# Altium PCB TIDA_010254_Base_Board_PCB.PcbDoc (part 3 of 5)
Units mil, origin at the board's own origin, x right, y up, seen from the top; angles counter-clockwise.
Board outline 3514.38 x 3143.81 mil, 4 copper layers (Top Layer, L2_GND1, L3_PWR1, Bottom Layer), stack 62.715 mil thick; 219 components, 146 nets, 618 pads, 2382 vias.
Unrouted connection lines stored in the file: 2280.
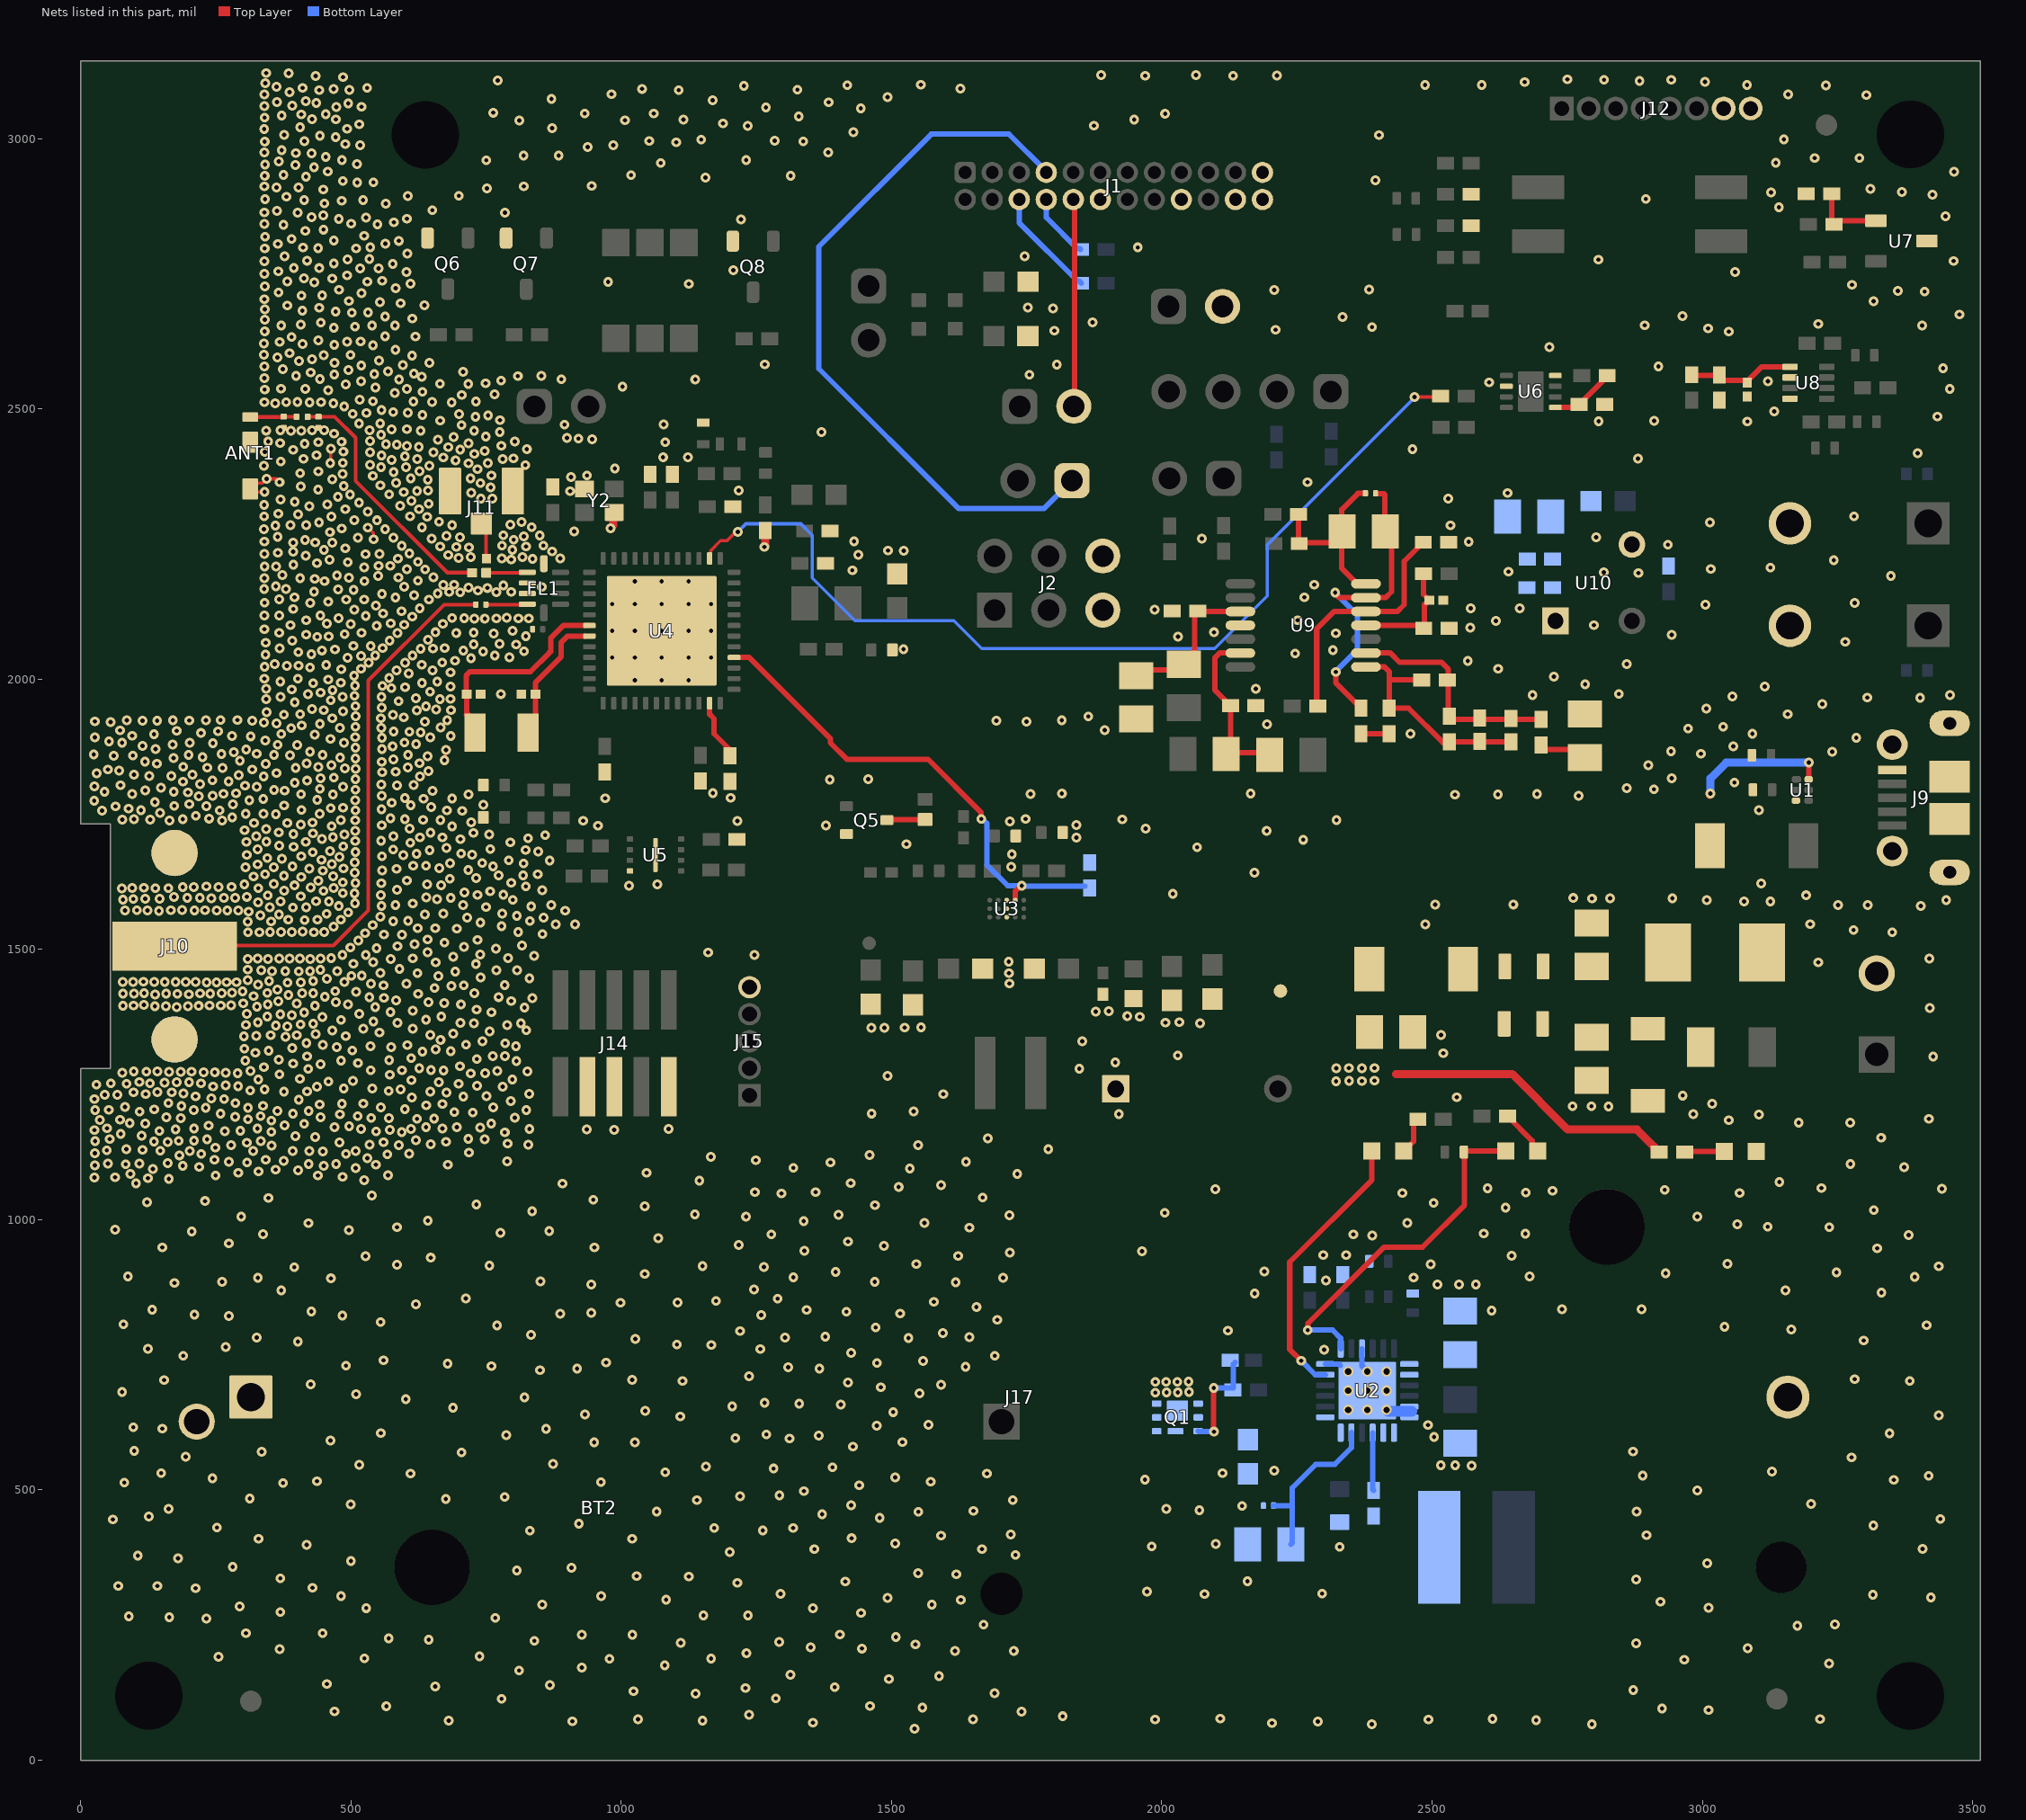
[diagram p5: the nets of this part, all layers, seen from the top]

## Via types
v1: diameter 18, hole 8, Top Layer to Bottom Layer, tented both sides, 2351 vias
v2: diameter 19.68, hole 7.87, Top Layer to Bottom Layer, 21 vias
v3: diameter 19.68, hole 11.81, Top Layer to Bottom Layer, 9 vias
v4: diameter 18, hole 8, Top Layer to Bottom Layer, tented bottom, 1 vias

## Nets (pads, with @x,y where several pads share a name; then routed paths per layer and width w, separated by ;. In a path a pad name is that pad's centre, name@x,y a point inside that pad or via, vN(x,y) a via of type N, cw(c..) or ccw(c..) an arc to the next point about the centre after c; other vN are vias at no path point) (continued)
GND: ANT1.2 ANT1.3 BT2.2 C1.2 C2.2 C4.2 C5.2 C6.2 C7.2 C8.2 C9.2 C10.2 C11.2 C12.2 C13.2 C14.2 C15.2 C16.2 C17.2 C18.2 C19.2 C20.2 C21.2 C22.2 C23.2 C24.2 C25.2 C27.1 C28.2 C32.2 C33.2 C34.2 C35.2 C36.2 C37.2 C38.2 C39.2 C40.2 C41.2 C42.2 C43.2 C44.2 C45.2 C47.2 C48.2 C49.1 C50.2 C51.2 C53.2 C55.2 C56.2 C57.2 C58.2 D6.2 D9.2 FL1.2 FL1.3 FL1.10 J1.12 J1.18 J1.22 J1.23 J1.24 J2.5 J2.6 J3.2 J8.2 J9.5 J9.6 J9.7 J9.8 J9.9 J9.10 J9.11 J10.2 J10.3 J10.4 J10.5 J11.2 J11.3 J12.7 J12.8 J14.3 J14.5 J14.9 J15.5 J17.1 Q5.2 Q6.2 Q7.2 Q8.2 R1.1 R2.1 R5.1 R10.1 R13.1 R16.1 R21.2 R22.1 R26.2 R31.2 R33.2 R36.1 R53.1 R59.1 R62.1 R75.1 R78.1 S1.2 S2.2 SW1.1 TP2.1 U1.3 U2.6 U2.9 U2.17 U2.18 U2.25 U3.C1 U3.C2 U3.C3 U4.49 U5.4 U5.9 U6.2 U6.8 U7.3 U8.2 U8.4 U9.11 U10.3 Y2.2 Y2.4 | length 368.6
  Top Layer w6: v1(289.66,1924.33) v1@290.3,1923.69 ; v1@316.49,1923.69 v1(317.13,1923.06) ; v1(324.89,1339.84) v1@325.59,1340.54 ; v1(339.32,2322.56) v1@340.36,2323.6 ; v1@340.74,2346.65 v1(340.36,2346.28) 319.25,2346.28 ANT1.2@313.66,2351.87 324.28,2362.49 336.02,2362.49 v1(344.15,2370.63) 361.66,2370.63 v1(367.83,2364.46) ; v1(341.99,2045.29) v1@342.05,2045.36 ; v1@342.05,2067.28 v1(342.12,2067.35) ; v1@350.89,1340.54 v1(351.58,1341.23) ; v1@364.18,2085.68 v1(367.12,2085.68) ; v1(417.3,2284.9) v1@417.84,2284.9 ; v1@455.89,2322.96 v1(456.43,2322.96) ; v1(461.77,2399.95) 462.43,2400.62 462.43,2425.93 v1(463.09,2426.6) ; v1(531.37,2280.34) 541.57,2270.14 541.57,2259.01 v1(541.94,2258.64) ; v1(574.96,2462) v1@575.16,2461.8 ; v1@575.16,2405.6 v1(575.36,2405.4) ; v1(609.39,2301.16) v1@609.39,2303.36 ; v1(673.09,1849.67) 674.58,1851.16 674.58,1867.47 v1(676.08,1868.96) ; v1(2794.73,1209.9) v1@2795.06,1209.58 ; v1@2826.17,1209.58 v1(2826.5,1209.26) ; v1@3404.02,1580.51 v1(3404.23,1580.51)
  Top Layer w10: ANT1.3@313.66,2438.48 314.2,2439.03 314.2,2439.26 ANT1.3@314.81,2439.87 ; v1@343.27,2443.35 v1(346.75,2439.87)
  Top Layer w15: v1(980.36,2279.08) 980.36,2279.9 985.48,2285.02 Y2.2@985.48,2307.51 ; v1(1264.52,2244.67) 1264.52,2245.48 1266.25,2247.21 C32.2@1266.25,2272.55
  Bottom Layer w6: 2460.02,648.33 2461.45,646.9
  Bottom Layer w10: U2.6@2302.44,732.97 2327.95,732.97 U2.25@2330.17,730.75 ; U2.9@2370.35,761.52 2370.35,729.04 v3(2380.19,719.19)
  Bottom Layer w20: U2.25@2418.41,645.89 2462.8,645.89
  other v1: 1542.39,58.46 2388.65,66.59 2795.65,66.73 2203.67,68.59 1354.37,69.52 909.53,71.98 2288.66,71.63 680.96,73.21 1150.38,73.21 2692.51,74.1 1987.42,75.24 2493.22,75.24 1031.18,75.67 1650.52,75.67 3217.6,76.18 2108.28,77.13 2611.81,76.38 1816.54,81.3 1236.4,84.27 1740.51,89.68 469.6,90.41 3011.7,92.88 2925.44,95.66 1557.09,97.26 565.48,100.06 1460.05,100.24 778.55,113.48 1286.04,114.32 1137.7,122.98 1690.65,124.21 1022.65,127.74 2872.08,129.57 1229.84,133.62 1394.88,135.12 656.07,136.28 867.91,139.13 455.6,141.17 1495.28,150.24 1587.85,155.54 1312.88,157.94 811.1,166.05 927.02,171.36 1080.53,175.56 3234.3,179.13 2966.44,185.95 978.1,187.58 1166.09,188.14 524.97,188.53 255.11,191.5 737.76,192.33 1231.74,198.03 1617.64,201.96 1726.12,201.96 368.23,205.63 1445.42,206.6 3084.04,206.96 1350.43,209.05 1544.4,214.14 2877.79,216.26 1110.15,217.03 1292.13,218.92 839.41,220.83 643.72,222.73 569.78,225.22 1507.95,227.82 927.24,232.27 1020.69,232.27 1404.67,232.66 305.72,235 447.53,235 3175.86,248.69 1670.3,250.86 3245.43,251.48 232.37,261.9 767.04,263.42 163.99,264.52 89.03,266.15 1151.96,267.87 1234.28,267.87 1443.43,272.32 369.29,274.12 1354.43,281.22 528.21,281.46 3011.7,282.08 294.14,284.47 853.81,287.89 1574.7,287.89 2922.66,293.21 1082.99,296.79 1628.05,296.5 1492.75,300.35 3422.64,301.17 481.76,303.46 962.84,303.47 3315.41,306 1294.71,307.92 2079.01,307.36 2296.5,308.11 1972.57,312.15 212.8,318.13 428.81,319.03 69.73,322.35 141.87,322.35 1214.74,328.23 1414.38,330.74 2158.43,331.29 2877.74,334.51 369.2,336.61 1124.98,339.97 1028.29,340.63 1619.67,343.85 1549.43,345.84 807,350.99 907.73,355.91 281.12,357.59 3009.04,364.16 500.05,368.49 180.36,373.38 105.8,378.56 1729.16,379.83 1200.76,385.07 1357.34,390.42 1667.33,390.49 3407.19,391.02 2329.12,394.83 1981.2,395.58 417.85,398.69 2099.61,399.93 1506.96,400.75 328.94,409.58 1020.13,409.59 1426.1,410.69 1591.87,415.44 2896.47,416.49 1720.37,417.64 830.88,424.66 1261.79,425.21 1171.96,429.72 1317.92,429.72 251.93,430.6 3316.37,434.49 921.52,437.55 59.5,445.38 3440.2,446.25 1478.24,448.29 126.08,450.63 1371.72,455.26 1065.59,460.02 1549.53,459.47 2878.27,460 1651.77,461.35 2069.42,462.71 162.84,464.96 2008.47,464.98 2148.49,470.5 1425.29,471.67 499.39,473.5 3200.91,474.08 1139.95,481.14 1724.26,481.14 312.83,483.97 675.37,483.41 784.42,486.95 1219.77,488.44 1292.63,490.06 1337.71,497.97 2990.89,499.17 1440.08,508.57 374.44,512.83 80.64,513.61 962.25,514.45 437.14,516.12 1572.59,515.39 1968.73,519.28 3353.94,518.6 243.73,521.58 1506.95,523.22 3418.78,526.27 2889.6,526.56 1676.63,530.19 149.04,531.01 609.94,530.38 2112.28,531.22 1081.36,532.9 3128.8,534.01 2208.15,535.68 1281.85,539.61 1390.72,541.82 1156.59,542.99 2573.17,545.12 2516.15,545.82 2542.79,545.59 515.15,546.32 873.58,548.07 3276.03,560.33 194.12,561.34 704.46,569.38 334.8,570.65 2871.54,571.19 99.09,572.33 1428.44,580.14 949.87,588.16 1025.39,588.02 1519.9,588.56 462.22,591.56 1211.18,596.03 1311.17,595.29 2503.74,597.89 1365.6,600.34 787.07,601.61 1268.53,602.59 555.18,605.08 3346.32,604.52 860.83,613.2 151.13,613.48 97.41,615.95 1472.77,618.86 2492.56,620.27 1568.15,620.54 1109.05,636.08 3437.42,638.24 932.89,639.43 1503.07,644.11 1044.48,646.59 688.79,652.02 1205.16,654.6 1406,658.13 1329.13,659.82 1265.06,661.46 601.55,667.95 821.06,671.46 509.28,677.18 1551.88,678.89 76.44,681.37 1480.06,690.12 1591.72,694.6 425.28,695.45 1419.46,698.53 1113.24,701.51 3383.57,701.67 154.46,703.18 1020.46,703.62 3281.6,705.02 1236.47,710.59 849.7,721.72 918.26,724.3 1366.72,724.34 1308.93,727.15 1636.93,727.61 760.09,729.19 490.76,730.07 678.67,733.73 1472.99,734.8 972.13,735.63 1558.26,738.67 560.34,739.8 189.76,748.15 1690.91,748.25 1425.08,753.52 2300.31,759.51 124.26,761.06 1257.37,760.71 268.31,764.44 1166.67,768.26 1102.91,769.02 401.91,774.48 3298.65,776.44 1026,779.52 1531.36,780.98 325.5,782.05 1302.76,782.13 1643.9,782.7 1377.38,783.82 833.23,786.73 1594.96,790.07 1219.78,794.06 2122.49,794.73 3164.73,796.84 1470.52,800.65 3040.87,801.93 770.17,804.52 3414.78,804.74 78.96,806.36 554.76,810.76 1695.52,814.68 273.93,821.8 484.24,822.91 210.36,824.25 1258.77,823.62 886.99,825.83 1515.98,826.41 944.31,827.45 426.77,830.24 1416.66,829.83 2610.04,831.67 1343.16,833.19 132.34,833.75 2887.54,834.14 2740.48,834.5 1657.08,838.6 620.2,843.38 998.78,846.27 1104.08,846.74 1578.16,848.13 1175.26,849.71 712.28,854.17 1289.29,853.95 2171.84,863.33 3331.31,864.99 371.12,869.19 3153.48,869.34 1245.59,870.86 2509.77,880 2549.66,880.19 2580.93,879.81 944.31,880.32 173.68,882.93 1618.65,884.25 261.79,884.9 1468.82,884.98 850.69,886.05 2303.64,887.48 462.94,891.45 327.72,892.71 1318.47,893.23 1706.18,892.67 2465.76,893.11 3392.9,894.23 87.35,895.28 2680.58,894.88 1043.25,899.56 2932.08,900.89 3248.21,902.58 1396.46,903.33 2189.91,904.32 395.15,911.95 1263.66,912.38 1150.49,914.08 3437.42,913.71 756.15,915.01 585.37,916.49 1546.03,917.97 2497.41,917.45 3046.66,918.2 647.78,929.72 526.94,932.66 1623.26,932.82 2647.19,933.19 2298.53,934.49 2341.06,934.69 1718.68,939.13 1963.68,941.8 1338.67,942.61 3323.34,947.1 151.13,948.58 950.58,948.63 1485.93,951.52 1217.52,953.18 273.93,956.28 1419.46,959.44 1068.35,965.59 2389.1,970.73 3381.39,971.69 1277.51,972.91 2354.2,972.86 337.5,973.39 2672.43,974.26 2595.56,974.38 776.25,975.52 205.47,978.28 866.74,978.87 496.33,980.49 63.86,981.68 1643.9,985.25 585.37,986.06 3234.77,986.2 3120.92,986.82 3064.56,991.62 421.5,993.47 1560.76,994 2454.27,993.87 1337.55,997.59 642.13,998.33 297.12,1005.64 1230.91,1005.53 2990.89,1005.8 1717.96,1008.25 1402.07,1008.81 1136.24,1010.03 2005.54,1012.79 835.09,1015.88 3317.17,1017.8 2636.06,1022.23 1043.5,1024.91 1469.11,1026.84 732.06,1028.29 2502.71,1030.91 122.95,1032.09 229.92,1034.52 948.29,1036.96 347.27,1040.32 1668.59,1040.94 538.42,1044.62 1296.59,1048.65 2444.92,1049.27 3068.92,1049.27 2673.25,1050.09 1247.21,1050.9 1359.43,1050.9 2722.71,1053.61 2930.43,1055.04 2099.15,1056.28 2602.78,1057.98 3443.18,1057.44 3220.38,1058.4 1513.18,1060.55 1591.72,1063.8 102.45,1067.24 891.44,1066.75 1424.51,1067.73 3142.47,1069.53 524.37,1072.84 1144.65,1072.31 162.92,1075.37 124.31,1076.64 25.56,1077.9 63.54,1078.54 484.49,1079.17 249.64,1081.7 438.91,1081.7 568.68,1082.33 92.03,1084.87 1732.55,1084.56 291.81,1086.85 1046.9,1086.79 328.77,1089.3 402.2,1091.2 360.42,1092.46 133.48,1094.08 1533.93,1094.66 508.54,1095.63 1318.47,1095.78 3373.41,1097.25 219.26,1097.53 188.87,1099.43 449.67,1099.43 26.19,1100.69 546.12,1101.76 679.06,1101.76 83.16,1102.59 421.82,1103.22 472.46,1103.22 3273.97,1103.06 50.25,1103.86 108.48,1103.86 161.02,1104.49 307.88,1105.76 1386.92,1105.88 274.33,1107.02 1637.73,1107.01 789.06,1108.09 375.61,1108.92 1248.99,1110.18 247.74,1110.82 342.06,1110.82 530.06,1113.98 1165.75,1116.32 182.54,1119.05 1459.43,1119.45 567.41,1120.95 223.06,1121.58 490.82,1121.58 26.12,1122.91 607.62,1122.34 718.16,1124.1 448.03,1126.14 201.53,1127.28 319.2,1127.09 392.27,1127.09 423.09,1127.28 508.83,1127.09 147.3,1127.45 48.28,1128.4 114.18,1129.18 84.51,1130.42 1790.02,1130.61 249.26,1133.35 352.91,1136.9 278.51,1137.97 588.32,1138.13 1549.08,1137.87 534.49,1138.67 827.84,1138.97 647.78,1139.74 789.66,1140.86 307.25,1142.47 478.79,1143.1 560.12,1143.23 161.02,1143.74 676.02,1144.18 135.7,1144.37 26.6,1145.49 181.4,1145.88 333.2,1145.63 209.74,1146.41 620.24,1146.84 53.74,1149.09 233.82,1148.8 747.26,1148.93 717.08,1149.38 1678.24,1150.51 3330.62,1151.6 433.71,1152.92 112.51,1155.27 397.04,1154.7 73.93,1158.9 593.9,1161.87 784.55,1161.71 352.6,1162.58 145.64,1164.22 266.76,1163.95 546.52,1163.36 295.19,1164.67 25.15,1165.9 986.81,1165.95 175.58,1167.16 571.64,1166.42 936.01,1166.92 518.5,1168 611.15,1168 830.25,1167.87 1087.44,1167.88 48.87,1169.13 209.74,1168.61 326.92,1168.93 669.28,1168.45 469.67,1171.13 638.85,1171.02 695.82,1171.02 738.85,1170.41 496.51,1172.85 236.73,1174.06 377.47,1174.63 119.53,1178.04 413.33,1177.39 759.5,1177.72 90.65,1178.65 3273.24,1179.27 3178.11,1179.74 352.73,1183.16 3048.99,1183.98 35.26,1184.5 72.79,1184.9 309.51,1185.86 622.09,1186.66 653.72,1186.78 3419.14,1186.53 185.07,1188 537.41,1188.13 570.46,1188.03 158.55,1189.28 803.31,1188.83 443.67,1189.58 285.63,1190.29 332.66,1191.65 512.37,1191.71 479.42,1195.01 1920.7,1195.07 2983.19,1195.08 3104.85,1194.52 258.84,1195.92 392.77,1196.34 1463.18,1196.4 691.35,1198.95 725.42,1198.33 109.1,1199.93 363.88,1201.18 1540.99,1200.42 421.82,1201.34 26.6,1202.65 52.25,1203.23 209.26,1203.06 824.45,1202.69 135.81,1204.15 599.75,1204.54 231.24,1207.03 309.42,1206.81 555.06,1207.89 763.41,1207.83 81.74,1208.76 186.48,1210.05 2759.73,1209.9 337.24,1210.58 639.46,1211.4 442.13,1213.07 669.21,1213.94 483.45,1214.32 522.7,1214.85 3017.92,1214.49 162.23,1215.83 286.16,1215.8 795.43,1219.38 403.32,1221.84 265.31,1223.23 25.15,1223.3 241.59,1224.19 612.4,1226.22 2545.55,1226.64 212.6,1228.02 708.02,1227.72 750.82,1228.45 2963.6,1229.68 44.62,1231.23 67.61,1231.19 120.15,1232.42 829.91,1232.53 1595.58,1232.32 190.08,1233.77 676.88,1234.98 97.83,1235.61 141.65,1236.23 168.27,1235.69 376.06,1236.72 418.71,1237.19 646.67,1236.93 569.83,1238.11 313.69,1238.87 340.09,1241.24 591.95,1241.14 486.74,1242.97 539.43,1242.97 436.91,1245.82 780.51,1245.83 245.19,1246.47 291.27,1246.88 733.01,1247.73 268.23,1248.7 29,1249.72 55.9,1252.22 85,1251.37 128.26,1252.22 222.42,1252.22 699.17,1251.45 155.09,1253.42 662.31,1254.2 108.37,1254.86 177.62,1254.38 200.38,1254.38 458.41,1255.64 503.48,1256.89 612.03,1258.16 328.57,1259.17 798.6,1259.27 405.55,1260.68 1492.55,1265.93 571.82,1268.21 367.64,1268.79 290.47,1270.91 721.8,1270.52 748.28,1271.25 76.78,1271.83 268.19,1271.63 227.45,1272.83 248.06,1272.59 98.07,1274.27 121.62,1273.79 141.83,1274.1 163.48,1273.31 185.04,1273.55 205.17,1273.79 826.26,1274.15 313.8,1275.05 770.67,1274.91 671.24,1276.03 536.65,1276.3 594.25,1276.3 648.08,1276.92 421.03,1278.86 1847.51,1279.23 626.41,1279.95 339.19,1282.19 701.89,1283.76 443.96,1287.72 393.25,1288.9 513.08,1289.6 1913.87,1291.04 806.16,1293.33 304.61,1294.39 481.57,1294.45 570.7,1295.02 366.54,1296.01 732.68,1297.26 611.54,1298.81 418.77,1302.16 3426.9,1301.68 762.46,1302.83 784.91,1302.8 2029.65,1303.84 2520.61,1308.08 323.22,1308.92 632.24,1311.13 684.65,1311.78 347.6,1312.61 502.55,1312.9 656.72,1315.13 302.69,1316.2 391.42,1317.61 473.51,1319.38 574.21,1319.49 536.03,1320.74 805.3,1320.72 447.76,1323.25 604.21,1322.95 712.72,1323.73 417.56,1326.71 785.19,1326.3 743.2,1330.01 1852.73,1329.83 665.61,1332.64 378.96,1338.45 301.97,1339.44 490.33,1339.52 399.76,1341.22 646.67,1341.94 2516.34,1341.65 434.42,1343.3 689.12,1344.18 552.83,1346.41 756.76,1348.42 465.46,1349.78 824.21,1350.32 522.66,1353.11 614.27,1353.11 1462.89,1354.94 1486.6,1354.94 1524.23,1355.42 1554.5,1355.62 382.48,1357.41 305.57,1360.28 361.15,1359.33 789.06,1359.82 406.92,1361.24 430.16,1362.44 814.24,1363.17 586.11,1363.94 727.52,1363.3 2070.8,1363.42 327.85,1364.84 702.56,1364.38 2006.68,1364.53 2032.33,1365.35 541.66,1366.44 481.56,1369.65 638.69,1370.2 447.14,1375.21 345.1,1375.62 667,1375.89 1959.45,1375.45 1936.25,1376.54 390.63,1378.25 369.3,1380.17 307.24,1380.89 515.54,1380.81 413.39,1383.53 572.99,1384.19 759.78,1383.57 1877.84,1385 1901.86,1385.55 614.47,1386.64 732.37,1388.77 820.94,1392.21 3420.52,1391.59 544.73,1393.1 177.86,1393.35 137.36,1394.79 157.49,1394.79 198.46,1394.79 326.17,1394.31 78.28,1395.84 218.11,1395.51 238.24,1396.23 259.32,1396.23 433.43,1395.8 97.55,1396.29 117.09,1397.2 278.25,1396.7 346.06,1398.14 494.71,1398.37 703.56,1398.32 399.73,1399.82 300.53,1400.3 672.75,1400.96 471.91,1402.62 643.34,1402.62 365.47,1403.89 796.66,1404.47 583.6,1405.88 835.46,1410.09 561.01,1410.3 534.15,1411.51 772.99,1411.84 451.72,1412.52 319.94,1413.72 384.4,1415.87 137.6,1416.35 200.14,1417.07 78.1,1418.28 98.54,1418 157.97,1418.27 178.81,1417.79 239.67,1418.03 624.29,1417.77 117.24,1419.23 220.75,1418.75 261,1419.23 409.79,1419.23 429.92,1418.99 728.44,1419.21 279.93,1419.95 345.34,1419.47 509.7,1421.67 299.58,1422.58 470.69,1422.9 363.79,1425.7 654.71,1428.73 686.05,1432.42 560.39,1433.65 708.66,1433.48 784.36,1434.26 328.09,1435.04 536.74,1436.72 602.48,1436.41 1718.19,1437.01 232.78,1439.26 251.28,1439.08 382.72,1438.64 407.16,1438.87 78,1439.81 96.86,1439.63 115.91,1440.18 135.88,1439.63 155.66,1439.81 175.45,1439.81 194.13,1439.63 212.63,1439.81 270.15,1439.45 288.33,1439.58 487.83,1439.68 348.46,1441.27 430.11,1441.57 308.93,1443.06 455.35,1445.79 830.14,1446.55 740.12,1448.4 500.79,1451.16 661.91,1450.42 519.84,1451.47 623.04,1455.96 1717.17,1456.18 554.18,1456.59 692.81,1459.15 354.2,1459.6 378.52,1459.6 403.57,1459.35 424.25,1459.77 474.37,1459.76 333.95,1461.46 769.11,1461.47 807.11,1461.47 309.25,1462.72 443.23,1462.3 589.86,1464.1 731.11,1472.87 504.73,1473.49 656.56,1476.05 3214.28,1476.17 541.35,1476.66 1716.73,1477.54 308.93,1482.06 346.34,1482.06 327.32,1483.01 367.51,1482.9 405.51,1482.9 424.4,1482.48 443.92,1483.1 573.3,1482.5 3419.82,1482.91 386.4,1483.31 463.44,1484.14 614.16,1483.42 790.81,1484.03 689.01,1486.32 838.74,1488.33 483.99,1489.54 527.52,1489.56 1246.68,1489.9 739.2,1490.79 641.82,1494.77 1160.72,1494.36 768.16,1501.37 547.49,1502.47 498.95,1503.45 709.09,1504.92 586.11,1506.04 816.61,1507.07 617.54,1509.84 672.84,1512.61 513.48,1516.54 733.96,1517.52 641.81,1518.44 561.01,1527.66 594.19,1527.35 854.41,1528.58 526.15,1530.03 309.53,1531.89 330.89,1531.89 350.3,1532.13 370.69,1532.13 431.35,1531.74 450.67,1532.22 809.24,1532.27 3351.15,1531.75 390.35,1532.37 410.26,1532.86 3279.65,1536 623.67,1539.22 655.82,1539.16 695.79,1538.49 467.84,1542 778.61,1543.17 540.47,1545.19 2487.47,1546.25 878.83,1546.3 914.59,1546.4 3199.57,1546.62 739.51,1549.47 308.8,1551.06 352.52,1551.76 577.97,1552.36 605.56,1553.16 830.86,1552.67 384.16,1555.13 414.12,1554.29 437.75,1555.13 480.96,1555.12 714.81,1558.67 856.56,1559 554.39,1560.35 332.26,1562.73 806.79,1562.38 366.86,1564.84 636.89,1564.83 455.02,1565.75 670.99,1566.37 780.06,1566.37 494.79,1568.24 310.74,1570 81.96,1572.09 123.6,1571.94 144.71,1571.45 210.49,1571.94 251.51,1572.05 271.07,1572.05 896.19,1571.59 104.15,1572.4 166.56,1572.43 187.68,1572.91 230.15,1572.67 291.58,1572.29 349.98,1577.92 392.6,1577.49 417.07,1577.92 750.11,1578.31 477.38,1580.16 833.51,1579.58 556.53,1580.55 582.21,1582.04 707.31,1581.84 870.38,1582.04 3250.84,1581.85 3306.13,1581.85 2505.76,1582.74 2650.23,1583.18 507.43,1585.17 614.28,1584.91 328.04,1587.2 369.82,1588.89 459.26,1588.75 3077.39,1588.98 3125.99,1588.98 435.24,1589.3 799.51,1591.61 3008.21,1591.48 3451.22,1591.41 78.36,1592.32 659.2,1592.68 97.21,1593.29 119.61,1593.53 145.77,1593.95 2795.79,1594.17 241.55,1594.79 2761.03,1595.14 2829.26,1594.49 2944.52,1594.78 197.24,1595.64 220.45,1595.64 265.18,1595.64 285.85,1595.64 639.35,1596.17 684.65,1595.53 172.77,1596.9 307.37,1597.32 407.37,1598.17 346.19,1599.86 3191.92,1600.13 555.46,1600.6 734.23,1600.75 782,1601.2 2020.39,1602.87 485.02,1604.25 506.72,1603.54 709.7,1605.39 757.63,1607.54 376.57,1608.72 449.24,1608.31 853.66,1609.66 584.97,1610.61 75.9,1612.96 95.23,1613.85 117.13,1613.99 138.17,1613.36 162.22,1613.36 328.47,1613.36 467.84,1613.55 425.51,1614.62 188.8,1615.47 209.06,1615.47 255.05,1615.47 279.1,1615.89 232.26,1616.73 823.4,1616.67 1014.35,1618.05 395.55,1618.42 666.9,1618.49 302.73,1620.11 1066.58,1620.14 640.89,1620.44 357.16,1621.37 3108.77,1622.09 508.15,1623.09 556.26,1622.52 796.65,1623.21 485.02,1624.05 439.62,1626.86 603.63,1627.48 682.92,1630.62 731.69,1631.98 408.21,1634.03 319.61,1634.88 467.13,1635.26 376.14,1636.14 772.91,1637.21 818.4,1637.14 341.12,1639.1 845.7,1638.96 506.96,1641.94 2171.16,1641.73 448.05,1645.75 557.87,1646.3 717.04,1646.92 422.98,1649.22 584.36,1649.01 485.97,1649.81 663.42,1650.27 304.84,1652.18 357.16,1651.75 1721.4,1652.69 391.76,1653.44 762.85,1653.62 615.39,1654.74 638.88,1655.01 327.2,1657.24 464.5,1657.92 683.53,1659.21 819.46,1659.06 742.88,1659.89 507.2,1661.26 867.7,1664.28 791.89,1664.8 445.26,1665.67 372.35,1667.79 345.12,1669.05 478.87,1670.83 408.21,1672.43 557.18,1672.44 307.37,1674.96 596.88,1674.66 724.24,1675.34 1722.73,1676.07 621.4,1676.72 703.75,1677.18 429.21,1679.73 508.39,1680.34 846.15,1681.27 461.38,1682.13 645.55,1683.79 822.95,1684 327.2,1685.09 578.18,1684.91 757.71,1685.66 676.82,1687.53 2065.36,1688.89 393.87,1689.73 485.85,1690.57 367.01,1691.96 1527.65,1694.72 609.8,1697.19 794.76,1698.01 306.53,1699.01 416.46,1698.85 343.66,1699.43 507.67,1700.61 555.74,1701.11 2261.67,1702.96 702.52,1703.9 446.05,1704.59 827.77,1705.71 627.67,1707.25 669.01,1707.25 1841.8,1706.97 466.54,1707.61 324.67,1709.14 578.52,1709.48 859.36,1711.31 487.89,1712.61 755.62,1712.66 393.57,1713.53 429.44,1714.68 647.01,1715.98 726.56,1715.63 366.44,1716.31 507.91,1719.21 2194.1,1719.54 303.15,1720.53 342.99,1722.71 608.39,1723.44 1970.34,1723.37 464.23,1727.97 686.98,1727.5 956.92,1728.96 556.92,1729.63 1378.84,1729.49 1841.8,1729.93 407.4,1731.04 320.87,1734.03 382.03,1733.9 428.96,1734.71 722.63,1735.18 1718.69,1737.04 261.38,1738.25 929.68,1738.09 1215.09,1737.79 164.19,1738.29 507.91,1738.77 2323.28,1739.08 77,1740.22 128.47,1739.94 481.28,1739.52 633.26,1739.64 665.53,1739.51 98.51,1741.21 188.81,1741.21 599.75,1740.76 1927.08,1740.65 237.75,1742.05 1748.02,1741.48 573.17,1742.4 280.37,1744.16 212.86,1747.11 361.01,1750.09 305.26,1750.91 338.21,1750.81 442.13,1750.81 146.61,1752.6 39.53,1756.76 257.16,1757.24 508.15,1757.14 677.75,1757.09 706.03,1756.34 111.43,1757.78 408.44,1758.1 3104.42,1757.48 556.6,1759.03 88.38,1760.61 462.36,1761.19 485.55,1762.22 648.37,1763.41 64.25,1764.63 232.69,1765.26 172.99,1765.38 376.31,1766.36 610.43,1766.79 281.63,1768.21 744.97,1767.57 201.12,1768.96 575.47,1771.46 137.27,1772.72 24.86,1775.11 312.01,1775.8 507.67,1775.74 437.54,1776.53 337.74,1778.64 634.38,1778.74 686.98,1778.99 599.75,1779.86 970.3,1779.69 1202.51,1780.47 218.34,1783.4 244.08,1784.24 2770.93,1783.99 556.69,1784.33 2542.49,1786.19 407.7,1787.11 466.54,1786.49 717.19,1786.61 2621.91,1786.61 95.33,1787.74 263.91,1788.04 1756.93,1787.53 2694.23,1787.69 287.54,1788.88 1815.12,1788.46 2164.24,1788.38 1169.48,1789.32 198.51,1790.57 44,1791.49 172.35,1791.84 650.88,1793.11 119.15,1794.28 377.23,1793.69 357.62,1795.25 508.15,1795.3 2910.32,1796.13 442.63,1797.02 2860.25,1798.23 148.72,1799.01 325.66,1800.69 485.39,1800.67 25.47,1801.88 303.99,1802.81 73.53,1803.71 585,1803.38 615.85,1804.05 556.1,1804.78 220.87,1805.76 395.97,1808.35 3059.42,1808.67 189.23,1810.4 273.61,1810.82 419.07,1812.23 243.66,1812.93 508.39,1815.09 1385.83,1814.31 1457.01,1815.24 443.75,1816.76 2943.42,1816.44 468.32,1817.96 338.71,1819.82 627.4,1819.9 126.63,1820.92 167.7,1820.68 292.6,1822.22 98.71,1823.35 206.75,1823.42 29.49,1825.93 362.31,1826.35 557.58,1827.89 582.63,1828.57 643.62,1829.8 70.91,1830.93 50.55,1832.89 317.56,1832.81 508.63,1833.94 488.73,1835.04 234.37,1836.14 262.64,1835.72 397.68,1835.94 605.01,1836.57 189.65,1837.83 439.7,1837.51 463.55,1840.61 2899.82,1840.6 342.12,1843.25 141.04,1843.68 417.99,1844.19 626.56,1844.65 557.14,1846.94 118.85,1847.51 294.36,1849.03 578.48,1851.39 508.39,1853.26 171.7,1854.09 480.09,1855.07 225.53,1855.97 61.06,1858.01 641.72,1857.65 96.38,1858.72 387.44,1859.07 199.76,1859.68 357.62,1859.73 447.43,1860.07 605.45,1859.98 24.23,1860.71 260.29,1861.81 325.89,1862 2997.39,1861.84 283.03,1864.85 424.34,1865.49 3240.05,1865.49 2942.02,1866.31 306.22,1870.02 138.35,1870.53 557.44,1870.65 508.39,1873.29 577.14,1875.6 3057.24,1875.54 114.29,1876.41 170.36,1879 364.31,1878.67 400.64,1878.34 620.59,1879.93 244.58,1881.67 76.69,1882.41 201.95,1882.33 486.93,1882.4 598.84,1882.8 52.5,1885.07 341.32,1886.33 461.96,1889.33 557.26,1891.38 646.93,1892.28 3284.61,1891.3 26.4,1892.33 507.91,1892.61 314.41,1894.27 280,1894.67 684.66,1894.65 95.38,1895.33 432.96,1897.33 135.7,1898.33 371.13,1898.67 2459.87,1898.84 3092.56,1899.23 222.48,1900.39 628.79,1901.63 578.91,1903.16 608.11,1902.65 254.21,1903.48 72.56,1905.1 177.73,1904.49 1894.23,1905.77 389.26,1909.26 2973.56,1908.57 479.62,1910 556.04,1909.79 665.66,1910.57 508.39,1911.93 3038.59,1911.99 408.64,1914.33 2194.67,1916.55 362.18,1918.13 442.58,1917.43 339.05,1919.8 55.11,1920.57 636.85,1921.26 26.2,1921.72 1749.6,1921.39 114.18,1923.06 141.37,1922.99 85.52,1923.72 170.69,1923.99 201.02,1923.66 231.48,1923.72 678.04,1924.1 1693.81,1923.31 1815,1923.95 258.67,1924.33 465.62,1927.66 555.3,1927.77 597.56,1929.39 1864.13,1930.88 508.63,1931.65 577.92,1934.16 375.98,1934.32 3157.76,1935.25 406.06,1935.31 343.79,1939.05 485.31,1940.78 621.84,1942.01 449.48,1942.7 684.83,1942.76 657.67,1943.73 427.96,1944.99 3007.13,1945.66 557.02,1947.09 508.15,1950.09 638.85,1949.67 3221.79,1953.75 396.06,1957.09 587.98,1959.43 462.6,1960.82 343.32,1962.98 664.54,1963.07 684.17,1963.6 620.03,1964.67 3305,1965.91 3402.96,1965.74 484.39,1967.02 556.57,1967.04 369.65,1967.31 3055.42,1968.15 506.48,1969.17 2685.82,1970.56 3458.27,1970.63 420.63,1972.31 777.54,1972.45 2845.51,1972.5 443.71,1974.96 646.33,1976.81 465.93,1979.9 390.48,1981.05 2174.05,1982.17 343.12,1982.37 574.82,1983.38 600.25,1984.95 683.93,1986.18 3115.37,1986.31 507.46,1988.22 558.04,1987.65 2783.1,1990.62 430.16,1992.5 631.41,1992.81 481.33,1993.44 659.63,1995.26 369.31,1995.64 457.81,1999.19 339.99,2000.97 401.64,2000.97 570.56,2001.89 2725.48,2004.45 505.77,2006.14 607.02,2010.34 684.42,2012.44 651.08,2016.1 584.3,2016.36 482.29,2018.31 518.65,2019.26 2622.2,2019.26 424.3,2021.63 340.12,2023.03 381.63,2024.63 403.26,2025.15 454.29,2026.3 631.17,2026.67 359.15,2027.89 2860.23,2028.09 532.88,2030.66 600.25,2030.35 668.71,2030.84 692.52,2034.28 2566.1,2033.67 721.96,2038.94 493.47,2039.71 792.89,2040.4 518.54,2043.1 544.77,2043.95 613.75,2043.85 766.11,2043.62 426.88,2046.27 2246.67,2047.55 402.64,2049.96 744.54,2051.46 820.14,2051.56 446.45,2053.14 707.95,2053.08 2316.64,2053.75 470.29,2054.96 1522.29,2055.24 367.98,2056.96 628.92,2056.29 651.54,2056.61 558.53,2057.47 673.34,2057.44 536.48,2061.01 504.67,2061.67 805.64,2064.22 726.87,2064.71 774.97,2065.22 3264.26,2069.18 391.47,2071.19 571.35,2071.23 642.54,2072.93 437.63,2078.29 458.95,2079.05 2029.84,2078.57 823.51,2079.35 2943.35,2081.76 416.97,2082.29 488.35,2083.35 586.04,2085.22 694.73,2085.07 764.17,2084.58 2322.05,2084.77 519.36,2085.68 726.87,2086.06 656.21,2086.71 2096.57,2086.71 799.02,2089.25 339.79,2092.35 2570.55,2095.36 547.5,2098.51 388.31,2099.95 2799.55,2099.79 598.34,2100.66 499.49,2101.93 455.27,2102.72 573.45,2103.17 670.16,2102.47 2617.98,2107.73 417.2,2109.16 2251.34,2108.91 728.23,2111.9 747.65,2112.08 476.95,2112.94 687.02,2113.15 709.5,2112.94 768.85,2112.37 809.54,2112.37 828.97,2112.37 787.91,2113.84 613.54,2115.59 527.27,2116.94 339.79,2117.67 367.31,2117.94 443.29,2117.94 559.33,2121.62 593.5,2125.55 506.31,2128.82 1986.59,2128.63 393.31,2129.94 627.28,2131.2 2571.29,2131.12 2662.27,2131.12 546.25,2136.14 3005.8,2137.92 424.63,2141.27 3281.83,2141.13 340.12,2141.33 457.75,2143.28 490.95,2147.27 644.14,2147.23 367.31,2147.94 524.38,2147.29 582.18,2150.93 395.53,2151.31 2263.59,2151.3 616.78,2154.97 557.27,2157.93 660.37,2158.53 701.94,2160.5 768.88,2161.15 431.63,2161.6 681.78,2161.46 796.25,2161.29 734.71,2164.04 504.98,2165 476.29,2165.93 339.46,2166.99 379.83,2166.9 752.51,2168.75 717.68,2169.4 598.7,2170.9 852.95,2170.45 360.98,2171.77 781.81,2173.68 671.04,2174.39 690.84,2174.67 2282.14,2174.72 524.94,2181.26 451.01,2181.5 623.91,2182.23 432.86,2185.43 339.65,2186.93 406,2186.86 496.28,2187.83 587.46,2187.96 652.34,2188.32 550.07,2191.05 3348.85,2190.91 474.29,2191.92 373.01,2192.36 2881.81,2196.41 2817.8,2197.6 2641.48,2198.78 1427.51,2201.29 603.36,2203.18 637.31,2202.99 3015.6,2203.83 3125.82,2206.24 524.41,2206.65 340.32,2208.59 361.28,2208.57 551.22,2209.69 572.63,2209.69 393.52,2211.92 437.16,2214.72 493.98,2216.19 623.75,2217.28 3243.07,2219.85 460.56,2220.75 796.4,2221.32 586.65,2222.97 835.99,2222.78 699.26,2224.25 778.75,2223.45 887.32,2223.53 721.56,2225.64 817.24,2225.65 416.3,2228.58 680.14,2229.68 1438.64,2230.02 526.79,2231.19 339.99,2231.91 553,2231.58 607.99,2232.31 364.98,2233.91 392.91,2235.64 872.29,2236.35 1493.6,2238.04 1522.62,2237.45 450.1,2238.99 798.6,2239.28 489.46,2242.02 718.24,2243.66 694.95,2244.47 665.11,2245.44 823.9,2245.51 594.06,2246.61 779.54,2246.98 855.96,2247.1 2936.35,2248.72 393.12,2252.46 433.66,2252.86 465.62,2252.58 2567.67,2254.14 339.65,2254.58 1430.69,2255.04 415.17,2257.61 801.04,2257.91 649.41,2260.17 2074.04,2260.14 513.04,2261.64 578.66,2261.64 2803.6,2262.23 364.31,2263.24 701.76,2262.3 819.52,2264.03 676.6,2264.94 781.92,2266.18 849.19,2266.04 460.99,2271.9 912.82,2273.12 338.79,2277.63 563.26,2277.4 482.63,2278.55 631.38,2280.63 834.45,2281.32 360.06,2284.31 387.9,2284.98 687.17,2284.73 2533.85,2284.65 794.62,2285.61 440.89,2289.79 3013.77,2290.18 815.55,2290.94 662.83,2291.29 506.08,2294.27 548.17,2293.83 463.56,2300.86 641.08,2300.45 3280.53,2301.22 339.46,2301.29 401.97,2304.9 365.65,2306.23 531.37,2310.03 489.52,2314.36 625.82,2314.53 422.97,2319.89 591.12,2320.66 643.71,2324.43 514.88,2326.52 395.93,2328.33 612.02,2329.77 369.65,2332.22 740.38,2334.14 761.5,2333.95 2529.91,2334.23 475.96,2337.36 498.38,2341.55 570.53,2341.85 722.3,2344.98 2639.5,2344.33 597.77,2345.94 622.2,2348.22 905.29,2347.81 642.56,2348.98 1217.43,2348.74 439.29,2350.54 758.46,2354.88 406.97,2356.55 486.65,2357.32 554.46,2358.42 739.62,2362.68 583.33,2363.34 2269.5,2364.48 642.02,2369.02 465.62,2369.88 610.42,2371.19 721.16,2371.63 907.22,2373.88 540.53,2376.01 759.98,2376.95 936.68,2376.82 484.75,2379.61 405.96,2380.91 578.85,2383.18 439.63,2384.21 626.83,2384.52 734.29,2388.37 988.14,2389.99 555.56,2392.49 602.06,2392.43 338.99,2394.54 644.89,2394.55 822.52,2396.02 535.34,2396.47 485.09,2400.27 717.54,2399.41 753.04,2399.95 370.31,2402.54 693.58,2404.91 622.62,2407.14 780.44,2407.06 411.97,2407.54 2881.05,2408.12 800.51,2408.35 670.92,2410.07 1077.34,2410.46 1123.52,2410.78 599.75,2412.16 436.47,2414.23 556.44,2413.61 728.39,2416.73 3398.47,2418.18 340.46,2420.26 535.4,2419.63 652.72,2419.85 485.95,2420.87 747.21,2422.22 393.12,2424.27 702.13,2424.91 825.31,2425.57 2463.67,2425.52 625.39,2429.43 680.05,2429.29 603.31,2431.2 778.09,2431.6 584.74,2434.08 564.73,2434.66 414.3,2435.53 717.26,2436.25 368.98,2436.86 439.63,2438.53 482.62,2439.2 1081.24,2438.37 803.01,2439.5 535.4,2440.53 660.77,2442.73 946.08,2444.01 920.92,2445.1 899.45,2446.19 690.16,2447.86 749.54,2448.67 555.77,2452.07 468.62,2454.19 775.18,2456.9 1370.52,2457.32 343.27,2459.88 388.97,2459.86 407.97,2459.52 450.29,2460.19 534.28,2460.28 629,2459.84 727.71,2459.78 369.31,2460.52 427.96,2460.52 603.63,2462.49 704.53,2470.08 895.04,2470.89 1078.42,2471.48 514.87,2472.79 554.01,2473.19 2808.01,2476.97 3083.27,2476.58 2910.64,2477.68 664.8,2478.37 775.76,2479.23 730.44,2485.43 3434.64,2485.81 753.74,2487.78 632.18,2488.55 503.14,2490.75 700.18,2490.58 528.87,2492.43 605,2493.11 578.12,2494 3132.88,2495.36 556.56,2497.74 487.38,2504.31 359.81,2510.18 467.42,2510.43 423.35,2511.98 686.17,2512.01 339.95,2512.31 380.28,2512.31 400.87,2512.74 444.86,2512.38 650.04,2512.65 540.78,2514.15 615.46,2513.84 731.2,2513.51 516.09,2517 705.18,2525.84 765.5,2526.9 580.86,2529.61 632.15,2531.52 458.11,2534.64 340.38,2535.84 415.28,2537.12 603.34,2537.22 3457.69,2537.03 370.81,2537.3 545.3,2539.52 1002.46,2541.19 490.18,2545.04 717.04,2546.22 664.52,2546.41 749.04,2547.44 2605.4,2548.91 518.54,2551.23 3121.32,2551.3 777.68,2552.33 1136.92,2554.28 588.97,2554.66 889.29,2554.8 442.63,2555.37 340.02,2556.73 631.03,2559.62 398.53,2560.88 808.68,2560.67 852.07,2561.1 1754.93,2563.25 469.28,2563.5 543.15,2564.43 616.28,2565.02 425.52,2567.22 568.73,2569.15 707.31,2568.79 495.45,2571.76 374.11,2573.6 3445.12,2575.15 339.65,2578.73 2918.6,2578.31 519.12,2580.18 596.13,2581.05 1805.84,2581.71 1265.71,2582.3 469.51,2585 645.26,2585.23 404.03,2588.55 551.83,2589.29 428.16,2591.89 364.07,2595.16 449.73,2599.19 613.12,2598.52 499.11,2599.62 338.85,2600.28 386.52,2603.01 582.16,2609.09 2716.99,2614.13 540.8,2617.58 469.05,2618.32 410.4,2620.15 338.92,2620.88 368.24,2623.82 493.07,2624.47 518.01,2624.64 439.68,2626.64 390.14,2633.02 563.13,2634.27 619.19,2633.95 340.38,2643.24 3048.8,2643.08 1801.25,2644.63 2210.3,2646.4 3010.7,2648.75 468.44,2649.91 507.54,2652.04 2388.75,2651.35 371.02,2654.05 538.92,2654.05 581.42,2654.05 3406.68,2654.02 2893.33,2654.55 407.29,2656.12 3214.56,2657.15 444.13,2659.74 1872.1,2659.82 340.75,2664.87 613.35,2667.1 2334.23,2669.83 563.11,2671.1 2963.27,2671.89 3475.72,2674.5 501.61,2677.89 531.59,2678.6 471.56,2680.1 410.03,2681.6 340.75,2684.3 1798.56,2685.75 441.5,2687.22 1752.14,2687.43 382.42,2691.36 635.97,2691.89 591.78,2695.51 553.43,2697.58 3316.91,2698.93 495.98,2699.44 339.65,2703 408.57,2709.59 446.63,2709.99 519.23,2714.17 365.94,2715.26 3411.05,2716.9 3361.88,2718.05 2208.23,2719.82 477.77,2720.39 2383.73,2720.96 582.56,2723.33 340.75,2726.82 3276.84,2729.62 1124.97,2731.15 610.26,2731.49 432.17,2733.86 975.77,2735.11 382.42,2735.93 530.42,2735.44 557.58,2736.97 465.56,2741.02 413.03,2741.63 492.96,2746.94 339.65,2749.92 602.74,2753.13 3060.37,2753.46 365.63,2754.37 1207.49,2756.41 517.16,2759.77 551.1,2759.64 394.18,2760.58 441.45,2760.46 577.27,2768.06 468.44,2769.1 340.02,2773.38 418.69,2774.28 3464.99,2773.56 2807.74,2776.08 493.8,2776.71 534.15,2777.33 1746.58,2782.09 377.23,2782.57 604.21,2787.52 340.38,2796.84 439.36,2797.21 509.74,2796.84 411.53,2798.66 535.81,2799.16 1955.56,2798.72 364.69,2805.27 563.78,2805.52 588.53,2810.88 468.44,2811.6 390.24,2814.43 341.12,2818.47 524.22,2820.16 415.58,2829.22 449.05,2831.68 375.16,2840.62 549.05,2841.49 340.02,2842.29 500.57,2842.69 579.62,2845.19 477.56,2851.19 1221.57,2850.7 603.61,2851.69 527.72,2853.81 427.39,2854.61 3449.81,2856.32 448.75,2858.24 401.6,2863.19 784.57,2863.22 340.02,2863.56 363.14,2866.41 650.62,2867.65 3141.77,2872.78 450.97,2880.06 564.58,2879.63 482.95,2885.19 413.51,2886.22 522.44,2886.28 341.12,2887.75 2895.59,2888.38 380.34,2892.44 605.07,2893.78 699.41,2894.27 3425.51,2896.23 3127.01,2900.28 3369.4,2901.44 448.75,2905.92 3310.97,2907.22 751.31,2908.02 362.52,2909.86 403.18,2909.55 340.02,2911.58 819.74,2911.83 945.47,2912.43 511.63,2918.83 541.51,2919.1 485.05,2921.59 2395.15,2923.13 1155.92,2927.73 416.62,2929.75 340.38,2931.01 1313.42,2931.11 375.16,2932.86 1018.06,2932.57 457.32,2939.07 3465.72,2938.91 431.73,2947.1 341.12,2952.27 396.97,2951.44 511.4,2952.81 1073.06,2954.95 3135.68,2955.24 366.25,2957.96 750.22,2959.91 1230.93,2960.11 483.25,2960.44 3207.6,2963.98 3290.42,2964.11 453.34,2965.98 819.37,2968.41 884.25,2968.49 427.26,2972.8 340.02,2974.26 398.21,2973.3 1382.64,2974.63 371.91,2978.66 937.83,2984.5 517.08,2987.76 985.42,2987.82 489.44,2989.89 1101.56,2993.12 340.38,2994.42 1336.62,2994.91 414.04,2995.51 1051.85,2995.67 1283.85,2996.3 1147.81,2998.13 3150.72,2998.63 471.56,3002.77 442.6,3005.02 376.25,3006.97 2401.56,3006.45 1429.41,3011.66 339.28,3017.88 492.87,3018.17 872.16,3019.27 406.01,3021.12 1233.96,3023.78 1874.58,3023.93 515.3,3026.48 1188.24,3028.17 811.44,3033.57 1006.72,3034.08 1114.95,3035.18 1948.81,3035.11 428.04,3035.79 471.88,3035.75 340.32,3039.08 1328.47,3040.92 371.91,3042.81 407.83,3044.86 453.46,3045.17 2006.12,3045.96 932.58,3046.46 1060.17,3046.46 763.41,3047.94 1443.2,3056.22 1267.67,3057.41 473.06,3058.3 519.25,3058.83 339.65,3060.41 391.38,3061.12 494.81,3065.03 435.77,3066 1383.66,3067.08 363.14,3067.83 416.52,3069.38 1169.07,3070.95 870.77,3073.31 1492.56,3076.74 3303.27,3080.61 340.02,3081.67 3158.76,3081.56 981.83,3082.31 386.21,3085.7 441.04,3089.55 496.91,3089.86 1106.4,3089.82 1325.92,3090.64 467.97,3091.86 1038.27,3092.02 1627.17,3092.82 410.4,3093.81 529.94,3093.81 362.1,3095.76 1226.91,3097.82 1418.34,3098.92 2487.14,3099.09 2591.77,3099.09 3082.62,3099.09 3228.51,3098.33 1554.1,3099.56 341.48,3102.56 2671.2,3104.57 3004.83,3105.11 2883.87,3106.61 771.48,3107.33 2818.02,3108.95 2942.37,3108.95 2750.09,3109.5 485.55,3113.93 434.59,3116.13 1969.51,3116.41 2131.81,3116.41 2212.97,3116.9 1887.86,3117.4 2063.03,3117.4 342.95,3121.26 384.74,3120.89
  other v2: 1025.23,1997.93 1074.83,1997.93 1124.44,1997.93 983.3,2039.85 1025.23,2039.85 1074.83,2039.85 1124.44,2039.85 1166.37,2039.85 983.3,2089.46 1025.23,2089.46 1074.83,2089.46 1124.44,2089.46 1166.37,2089.46 983.3,2139.07 1025.23,2139.07 1074.83,2139.07 1124.44,2139.07 1166.37,2139.07 1025.23,2181 1074.83,2181 1124.44,2181
  other v3: 2344.76,648.33 2380.19,648.33 2415.63,648.33 2344.76,683.76 2380.19,683.76 2415.63,683.76 2344.76,719.19 2415.63,719.19
HDC_INT: R43.2 U4.38 | length 1775.5
  Top Layer w6: U4.38@1163.41,2223.32 1165.14,2225.04 1165.14,2237.51 1183.83,2256.2 1195.7,2256.2 1206.13,2266.63 1206.31,2266.63 1212.31,2272.63 v1(1215.55,2272.63) ; v1(2467.45,2522.04) 2514.01,2522.04 R43.2@2514.85,2522.88
  Bottom Layer w6: v1(1215.55,2272.63) 1215.78,2272.63 1230.52,2287.36 1332.25,2287.36 1353.35,2266.26 1353.35,2187.24 1432.4,2108.2 1615.23,2108.2 1666.85,2056.57 2097.55,2056.57 2195.07,2154.09 2195.07,2248.28 v1@2467.87,2521.08
LVDS_D0_LIN_PHY_RX: J1.7 J7.1 | length 1359.4
  Bottom Layer w10: J1.7@1786.76,2938.92 1717.31,3008.36 1573.6,3008.36 1365.43,2800.18 1365.43,2574.36 1624.45,2315.34 1781.9,2315.34 J7.1@1833.87,2367.31
LVDS_D1_XDS_UARTA_RX_CAN_RX: J1.6 R68.1 | length 204.7
  Bottom Layer w10: J1.6@1736.28,2887.4 1736.28,2844.31 1843.64,2736.95 1846.55,2736.95 R68.1@1851.4,2732.11
LVDS_D2_XDS_UARTA_TX_CAN_TX: J1.8 R67.1 | length 125.9
  Top Layer w6: J1.8@1786.76,2884.18 J1.8@1786.76,2888.92
  Bottom Layer w10: J1.8@1786.28,2887.4 1786.28,2854.2 1844.15,2796.34 1848.45,2796.34 R67.1@1849.78,2795.01
LVDS_FRCLK_HOST_CLK_TP: J1.10 J16.2 | length 455.4
  Top Layer w4: J16.2@1833.03,2504.41 J16.2@1843.34,2514.73 ; J16.2@1838.34,2509.72 J16.2@1843.34,2514.73 ; J16.2@1839.48,2510.86 J16.2@1843.34,2514.73 ; J16.2@1839.19,2510.57 J16.2@1843.34,2514.73 ; J16.2@1839.19,2510.57 J16.2@1843.34,2514.73 ; J16.2@1839.19,2510.57 J16.2@1843.34,2514.73 ; J16.2@1839.19,2510.57 J16.2@1843.34,2514.73
  Top Layer w10: J16.2@1836.59,2523.62 J16.2@1836.59,2530.33 ; J16.2@1836.76,2523.62 J16.2@1836.76,2530.33 ; J1.10@1836.76,2882.33 J1.10@1836.76,2888.92 ; J16.2@1839.05,2523.62 1839.05,2530.33 1839.05,2882.33 J1.10@1839.05,2888.92 ; J16.2@1840.04,2509.72 J16.2@1840.04,2514.6 ; J16.2@1840.04,2509.72 J16.2@1840.04,2514.6 ; J16.2@1840.04,2509.72 J16.2@1840.04,2514.6 ; J16.2@1840.04,2509.72 J16.2@1840.04,2514.6
MODE: R53.2 U3.B1 U4.28 | length 913.6
  Top Layer w10: U4.28@1208.69,2040.25 1236.78,2040.25 1386.85,1890.18 1386.85,1882.38 1417.42,1851.81 1567.45,1851.81 1666.03,1753.23 v1(1666.03,1741.26) ; U3.B1@1728.94,1591.15 1728.94,1607.45 1739.34,1617.85 v4(1741.07,1617.85)
  Bottom Layer w10: v1@1666.27,1743.36 1676.1,1733.53 1676.1,1656.73 1714.98,1617.85 v4(1741.07,1617.85) ; v4@1741.53,1617.39 R53.2@1857.89,1617.39
NetANT1_1: ANT1.1 C30.2 C34.1 | length 85.4
  Top Layer w7: ANT1.1@313.66,2484.94 374.82,2484.94 C34.1@375.46,2485.58 ; C34.1@375.81,2485.23 C30.2@399.2,2485.23
NetC3_1: C3.1 L3.1 U2.19 U2.20
NetC3_2: C3.2 U2.21 | length 107.7
  Bottom Layer w10: U2.21@2389.85,605.82 2389.85,501.02 C3.2@2391.91,498.96
NetC5_1: C5.1 D4.1 D10.1 Q1.1 Q1.2 Q1.5 Q1.6 Q1.8 R12.1 U1.6 U2.1 | length 804.3
  Top Layer w10: U1.6@3196.68,1817.18 v1@3196.68,1848.12
  Top Layer w15: 2433.59,1269.65 2648.14,1269.65 2750.8,1166.99 2879.03,1166.99 2911.62,1134.4 2911.62,1129.42 2914.89,1126.15 R12.1@2919.87,1126.15 ; v1@3014.03,1786.15 v1@3014.93,1787.05 ; v1@3196.7,1845.59 v1(3196.8,1845.7)
  Bottom Layer w15: v1@3014.93,1787.05 3014.93,1816.32 3044.3,1845.7 v1(3196.8,1845.7)
  other v1: 1987.97,680.02 2008.87,680.5 2029.6,680.65 2050.33,681.13 1988.01,699.85 2008.07,699.95 2028.8,700.11 2049.53,700.59 2322.39,1256.22 2346.41,1256.66 2370,1256.52 2393.29,1257.39 2370.15,1280.1 2322.83,1280.39 2346.12,1280.54 2393.29,1280.69 3014.79,1788.24
NetC6_1: C6.1 Q1.4 Q1.7 U2.24
NetC7_1: C7.1 C10.1 C45.1 D9.1 F1.1 FB1.1 FB2.1
NetC9_1: C9.1 C49.2 U2.23 | length 308.6
  Bottom Layer w10: C49.2@2206.73,471.19 2240.3,471.19 2241.39,472.28 ; C9.1@2239.08,399.42 2241.39,401.73 2241.39,472.28 ; U2.23@2350.67,606 2350.67,578.09 2319.97,547.39 2284.65,547.39 2241.39,504.14 2241.39,472.28
NetC11_1: C11.1 J17.2 U2.13 U2.14
NetC26_1: C26.1 J10.1 | length 978.4
  Top Layer w7: J10.1@263.09,1507.29 467.55,1507.29 532.13,1571.88 532.13,1997.58 672.5,2137.95 C26.1@730.87,2137.95
NetC26_2: C26.2 FL1.4 | length 76.9
  Top Layer w6: FL1.4@825.47,2137.95 FL1.4@826.18,2138.66
  Top Layer w7: C26.2@749.57,2137.95 FL1.4@825.47,2137.95
NetC29_1: C29.1 J11.1 | length 50.3
  Top Layer w7: J11.1@749.91,2273.1 749.91,2223.65 C29.1@750.54,2223.02
NetC29_2: C29.2 C31.1 FL1.1 | length 76.3
  Top Layer w7: C31.1@750.2,2196.88 825.35,2196.88 FL1.1@826.18,2197.71
NetC30_1: C30.1 C31.2 C33.1 | length 470.1
  Top Layer w7: C30.1@419.87,2485.23 C33.1@439.71,2485.23 ; C33.1@440.03,2485.54 469.79,2485.54 508.55,2446.78 508.55,2366.74 678.13,2197.17 C31.2@723.92,2197.17
NetC35_1: C35.1 U4.23 | length 98.7
  Top Layer w10: U4.23@1163.41,1955.6 1163.41,1935.03 1171.63,1926.81 1171.63,1899.03 C35.1@1199.04,1871.61
NetC36_1: C36.1 U4.6 Y1.1 | length 396
  Top Layer w6: Y1.1@711.66,1933.61 712.67,1933.61 729.35,1916.93 Y1.1@729.35,1901.18
  Top Layer w10: C36.1@712.99,1973.41 712.99,2006.59 720.33,2013.93 832.17,2013.93 866.83,2048.59 ; C36.1@713.91,1972.42 713.91,1937.54 Y1.1@718.76,1932.69 ; 866.59,2048.84 869.29,2051.53 869.29,2075.78 892.81,2099.3 U4.6@940.97,2099.3
NetC37_1: C37.1 U4.7 Y1.2 | length 240.3
  Top Layer w6: Y1.2@827.78,1901.18 Y1.2@834.38,1907.78
  Top Layer w10: Y1.2@841.48,1906.86 841.48,1972.46 841.48,1994.2 889.07,2041.78 889.07,2068.2 900.7,2079.83 U4.7@934.16,2079.83
NetC39_1: C39.1 R42.1 U7.1 | length 143.7
  Top Layer w10: C39.1@3243.53,2893.76 C39.1@3239.55,2897.74 3239.55,2845.47 R42.1@3243.53,2841.49 3250.05,2848.02 U7.1@3321,2848.02
NetC40_1: C40.1 R41.1 U6.5 | length 120.3
  Top Layer w6: C40.1@2766.41,2502.56 C40.1@2772.11,2508.25
  Top Layer w10: U6.5@2728.04,2502.56 C40.1@2766.41,2502.56 ; C40.1@2772.11,2508.25 2814.69,2550.84 2815.14,2550.84 R41.1@2815.14,2564
NetC41_1: C41.1 C42.1 R58.2 U8.1 | length 198.1
  Top Layer w10: R58.2@2981.04,2562.08 3030.97,2562.08 3031.27,2562.39 C41.1@3031.27,2563.1 3031.27,2559.42 3038.09,2552.61 3085.84,2552.61 3086.04,2552.81 3086.04,2554.2 3109.23,2577.4 U8.1@3160.68,2577.4
NetC46_1: C46.1 C54.2 D11.1 D12.2 R11.2 U9.1 | length 426.7
  Top Layer w10: U9.1@2377.59,2022.76 2412.09,2022.76 2420.67,2014.18 2420.67,1998.42 C54.2@2420.67,1946.23 2456.64,1946.23 2520.17,1882.7 2530.61,1882.7 R11.2@2531.99,1884.07 2588.17,1884.07 D11.1@2645.81,1884.07 ; 2420.8,1998.42 C46.1@2480.86,1998.42
NetC46_2: C46.2 D11.2 D12.1 R4.2 R11.1 U9.2 | length 426.7
  Top Layer w10: U9.2@2377.59,2048.35 2422.68,2048.35 2440.11,2030.91 2517.49,2030.91 2529.49,2018.92 2529.49,1930.5 2534.49,1925.49 R4.2@2701.6,1925.49
NetC47_1: C47.1 C48.1 C50.1 R3.1 U10.1
NetC51_1: C51.1 R4.1 | length 92.1
  Top Layer w10: R4.1@2701.6,1878.25 2701.6,1876.78 2708.41,1869.97 2771.1,1869.97 C51.1@2784.01,1857.06
NetC52_1: C52.1 R8.1 R56.2 U9.6 | length 581.3
  Top Layer w10: v1@2321.41,2158.93 2321.41,2158.3 2321.09,2157.98 2328.36,2150.71 U9.6@2377.59,2150.71 2413.88,2150.71 2425.06,2161.88 2425.06,2253.65 2412.93,2265.78 2412.93,2341.5 2411.01,2343.42 2396.76,2343.42 C52.1@2395.91,2344.27 ; v1@2321.81,2014.26 2321.81,1993.11 R56.2@2368.7,1946.23
  Bottom Layer w10: v1@2321.41,2158.93 2362.25,2118.1 2362.25,2054.7 v1@2321.81,2014.26
  other v1: 2321.82,2013.34 2320.82,2159.99
NetC52_2: C52.2 R8.2 R54.1 R57.1 U9.7 | length 383.3
  Top Layer w10: R54.1@2252.95,2305.11 2252.95,2252.8 2252.49,2252.34 2319.49,2252.34 R8.2@2332.93,2265.78 ; C52.2@2376.91,2343.84 2362.87,2343.84 2332.93,2313.9 R8.2@2332.93,2265.78 ; U9.7@2400.5,2177.46 2360.36,2177.46 2332.93,2204.89 R8.2@2332.93,2265.78
NetC53_1: C53.1 R6.1 R55.2 U9.13 | length 332.8
  Top Layer w10: R55.2@2118.91,1861.26 R55.2@2122,1864.36 ; U9.13@2145.3,2048.35 2107.06,2048.35 2098.4,2039.68 2098.4,1979.55 C53.1@2126.99,1950.95 2126.99,1869.34 R55.2@2122,1864.36 ; R6.1@2210.74,1864.36 2126.99,1864.36 R55.2@2122,1864.36
NetC54_1: C54.1 R56.1 | length 52
  Top Layer w10: R56.1@2368.7,1898.98 C54.1@2420.67,1898.98
NetC55_1: C55.1 R60.1 U9.5 | length 461.9
  Top Layer w10: R60.1@2286.86,1950.1 2286.58,1950.38 2286.58,2093.25 2318.45,2125.12 U9.5@2377.59,2125.12 ; U9.5@2377.74,2124.97 2435.65,2124.97 2448.33,2137.65 2448.33,2218.06 C55.1@2489.46,2259.19
NetC56_1: C56.1 R61.1 R62.2 U9.10 | length 264.5
  Top Layer w10: R62.2@1949.3,2013.33 R62.2@1950.4,2012.23 ; R62.2@1952.66,2006.24 1963.28,2016.85 R61.1@2025.47,2016.85 ; R61.1@2040.87,2033.63 2060.52,2053.27 2060.52,2126.07 2061.47,2125.12 U9.10@2145.3,2125.12
NetC57_1: C57.1 C58.1 R63.2 U9.4 | length 222.1
  Top Layer w10: U9.4@2377.97,2099.15 2479.61,2099.15 C57.1@2484.6,2094.16 2485.77,2095.32 2485.77,2138.9 2487.58,2138.9 C58.1@2494.81,2146.14 2484.17,2156.78 R63.2@2484.17,2197.89
NetD1_2: D1.2 Q1.3 R9.1 | length 195.7
  Top Layer w10: v1(2096.09,688.59) 2096.09,685.01 2095.98,684.9 2095.98,608.15 v1(2096.31,607.81)
  Bottom Layer w10: Q1.3@2067.39,608.75 2067.88,608.26 2095.86,608.26 v1(2096.31,607.81) ; v1(2096.09,688.59) 2123.67,688.59 2123.78,688.49 2132.66,688.49 2132.35,732.83 D1.2@2135.54,736.02
NetD2_1: D2.1 R7.2 | length 70.9
  Top Layer w10: D2.1@2447.86,1126.97 2465.88,1144.98 R7.2@2465.88,1190.36
NetD2_2: D2.2 U2.5 | length 514.7
  Top Layer w10: v1@2257.89,738.97 2236.68,760.18 2236.68,921.58 2388.81,1073.71 D2.2@2388.81,1126.97
  Bottom Layer w10: v1@2258.14,738.87 2283.72,713.29 U2.5@2302.44,713.29
  other v1: 2258.14,738.97
NetD4_2: D4.2 FB1.2 FB2.2
NetD5_1: D5.1 R15.1 | length 73.4
  Top Layer w10: R15.1@2639.69,1191.59 2685.18,1146.1 D5.1@2685.18,1137.05
NetD5_2: D5.2 R52.2 U2.7 | length 655.9
  Top Layer w10: v1(2270.01,795.66) 2270.41,796.05 2270.41,808.39 2411.45,949.43 2482.49,949.43 2560.05,1026.99 2560.05,1124.01 R52.2@2558.95,1125.11 2560.81,1126.97 D5.2@2636.03,1126.97
  Bottom Layer w10: v1(2270.01,795.66) 2316.07,795.66 2330.98,780.75 U2.7@2330.98,761.52
NetD6_1: D6.1 R12.2 | length 74.3
  Top Layer w10: R12.2@2967.11,1125.11 2968.58,1126.58 D6.1@3040.79,1126.58
NetD7_1: D7.1 Q5.3 | length 71.2
  Top Layer w10: Q5.3@1491.49,1739.21 1492.67,1740.4 D7.1@1562.16,1740.4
